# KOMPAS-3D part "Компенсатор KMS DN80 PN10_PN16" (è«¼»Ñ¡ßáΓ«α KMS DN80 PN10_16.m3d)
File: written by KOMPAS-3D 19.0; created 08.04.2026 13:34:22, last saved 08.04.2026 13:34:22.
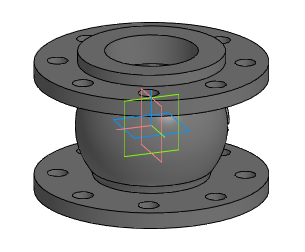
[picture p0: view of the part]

Document properties: Автор: Энергия; Полное имя файла: Z:\3.Личные\kachalov\3d для проектировщиков\7.1 Компенсатор\stp_Компенсатор KSM\Компенсатор KMS DN80 PN10_16.m3d

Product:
- Part/product: Компенсатор KMS DN80 PN10_PN16

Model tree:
1. Операция без истории:1  (labels: Компенсатор KMS DN80 PN10_PN16)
